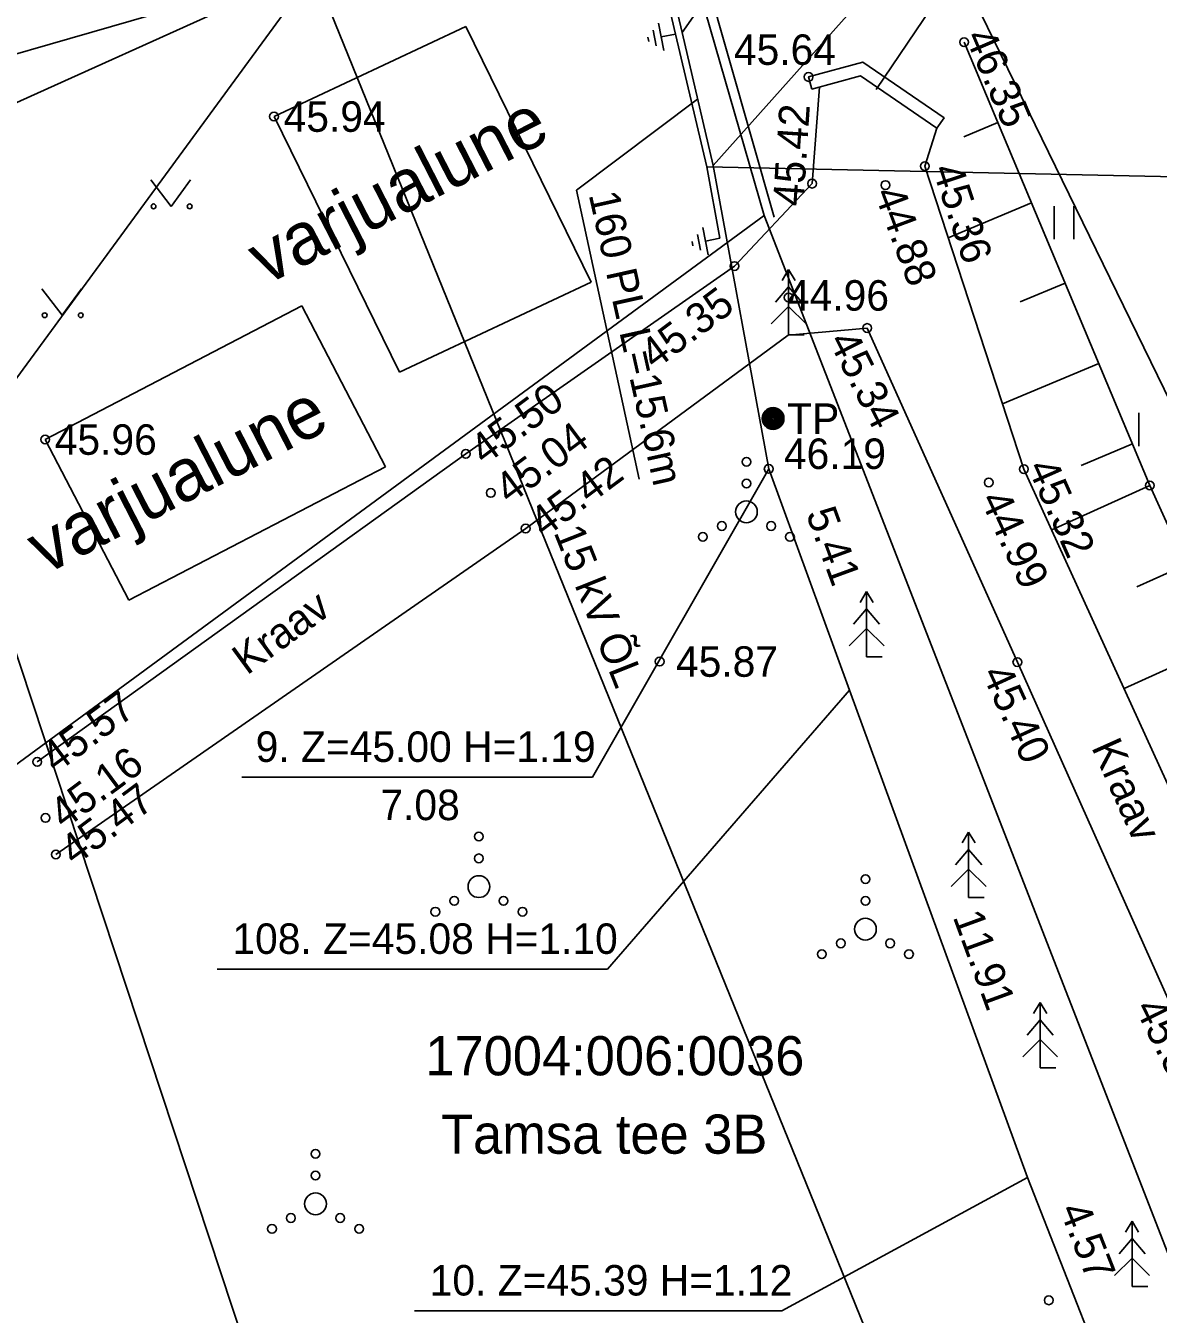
# Model space of a CAD drawing. Extents: x 642747 to 644424, y 6457048 to 6458238.
# Drawn here: x 644056.64 to 644082.64, y 6457705.93 to 6457735.52 of the extents above; entities that cross this region are included whole.
import ezdxf

# ---------------------------------------------------------------- set-up
doc = ezdxf.new("R2010")
doc.units = 0
for name, color, linetype in [('ABIJOONIS', 7, 'Continuous'), ('AED', 7, 'Continuous'), ('HALJASTUS', 7, 'Continuous'), ('HOONE', 7, 'Continuous'), ('JOONSIDE', 7, 'Continuous'), ('KOORDPUNKT', 7, 'Continuous'), ('KORGUS', 7, 'Continuous'), ('KPKAABEL', 7, 'Continuous'), ('KPOHULIIN', 7, 'Continuous'), ('MOOTPIIR', 7, 'Continuous'), ('MPKAABEL', 7, 'Continuous'), ('PIIR', 7, 'Continuous'), ('POST', 7, 'Continuous'), ('PUU', 7, 'Continuous'), ('RELJEEF', 7, 'Continuous'), ('TEE', 7, 'Continuous'), ('TRUUP', 7, 'Continuous'), ('VEEKOGU', 7, 'Continuous')]:
    doc.layers.add(name, color=color, linetype=linetype)

msp = doc.modelspace()

# ---------------------------------------------------------------- linework, layer by layer
at = {"layer": 'ABIJOONIS'}
for points in [[(644045.404, 6457721.568), (644052.131, 6457721.568), (644063.341, 6457736.874)], [(644039.301, 6457733.324), (644051.051, 6457733.324), (644062.377, 6457736.596)], [(644072.06, 6457733.834), (644069.281, 6457731.738), (644070.716, 6457725.107)], [(644072.272, 6457732.277), (644083.05, 6457732.046), (644093.848, 6457732.046)]]:
    msp.add_lwpolyline(points, dxfattribs=at)
at = {"layer": 'AED'}
msp.add_lwpolyline([(644064.587, 6457759.915), (644069.655, 6457745.733), (644073.82, 6457731.123)], dxfattribs=at)
at = {"layer": 'HALJASTUS'}
for p, q in [((644059.508, 6457731.975), (644059.971, 6457731.369)), ((644059.971, 6457731.369), (644060.417, 6457731.975)), ((644080.243, 6457731.376), (644080.243, 6457730.615)), ((644080.698, 6457731.376), (644080.698, 6457730.615)), ((644057.008, 6457729.475), (644057.471, 6457728.869)), ((644057.471, 6457728.869), (644057.917, 6457729.475)), ((644082.193, 6457726.628), (644082.193, 6457725.867))]:
    msp.add_line(p, q, dxfattribs=at)
for centre, radius in [((644059.57, 6457731.369), 0.055), ((644060.399, 6457731.369), 0.055), ((644057.07, 6457728.869), 0.055), ((644057.899, 6457728.869), 0.055), ((644073.181, 6457725.505), 0.1), ((644073.181, 6457725.005), 0.1), ((644073.181, 6457724.355), 0.25), ((644072.616, 6457724.03), 0.1), ((644073.746, 6457724.03), 0.1), ((644072.181, 6457723.78), 0.1), ((644074.181, 6457723.78), 0.1), ((644067.039, 6457716.899), 0.1), ((644067.039, 6457716.399), 0.1), ((644067.039, 6457715.749), 0.25), ((644075.913, 6457715.923), 0.1), ((644066.474, 6457715.424), 0.1), ((644067.604, 6457715.424), 0.1), ((644075.913, 6457715.423), 0.1), ((644066.039, 6457715.174), 0.1), ((644068.039, 6457715.174), 0.1), ((644075.913, 6457714.773), 0.25), ((644075.348, 6457714.448), 0.1), ((644076.478, 6457714.448), 0.1), ((644074.913, 6457714.198), 0.1), ((644076.913, 6457714.198), 0.1), ((644063.289, 6457709.616), 0.1), ((644063.289, 6457709.116), 0.1), ((644063.289, 6457708.466), 0.25), ((644062.724, 6457708.141), 0.1), ((644063.854, 6457708.141), 0.1), ((644062.289, 6457707.891), 0.1), ((644064.289, 6457707.891), 0.1), ((644080.121, 6457706.251), 0.1)]:
    msp.add_circle(centre, radius, dxfattribs=at)
at = {"layer": 'HOONE'}
for points in [[(644062.335, 6457733.431), (644066.739, 6457735.497)], [(644066.739, 6457735.497), (644069.618, 6457729.631)], [(644062.335, 6457733.431), (644065.214, 6457727.565)], [(644065.214, 6457727.565), (644069.618, 6457729.631)], [(644057.08, 6457726.015), (644062.977, 6457729.083)], [(644064.897, 6457725.392), (644062.977, 6457729.083)], [(644059, 6457722.324), (644057.08, 6457726.015)], [(644059, 6457722.324), (644064.897, 6457725.392)]]:
    msp.add_lwpolyline(points, dxfattribs=at)
at = {"layer": 'KOORDPUNKT'}
for p, q in [((644071.702, 6457735.361), (644074.389, 6457739.182)), ((644063.341, 6457736.874), (644051.03, 6457731.321)), ((644072.419, 6457732.308), (644076.502, 6457736.885)), ((644073.692, 6457725.34), (644069.649, 6457718.263)), ((644075.548, 6457720.26), (644069.989, 6457713.855)), ((644061.599, 6457718.263), (644069.649, 6457718.263)), ((644061.03, 6457713.855), (644069.989, 6457713.855)), ((644079.636, 6457709.071), (644073.995, 6457706.011)), ((644065.56, 6457706.011), (644073.995, 6457706.011))]:
    msp.add_line(p, q, dxfattribs=at)
for points in [[(644071.702, 6457735.361), (644071.702, 6457735.361), (644071.702, 6457735.361)], [(644072.419, 6457732.308), (644072.419, 6457732.308), (644072.419, 6457732.308)], [(644073.692, 6457725.34), (644073.692, 6457725.34), (644073.692, 6457725.34)], [(644075.548, 6457720.26), (644075.548, 6457720.26), (644075.548, 6457720.26)], [(644079.636, 6457709.071), (644079.636, 6457709.071), (644079.636, 6457709.071)]]:
    msp.add_lwpolyline(points, dxfattribs=at)
at = {"layer": 'KORGUS'}
for centre in [(644078.177, 6457735.139), (644074.609, 6457734.34), (644062.335, 6457733.431), (644077.278, 6457732.291), (644074.688, 6457731.891), (644076.371, 6457731.859), (644072.906, 6457729.999), (644074.15, 6457729.278), (644075.952, 6457728.576), (644057.08, 6457726.015), (644066.738, 6457725.687), (644073.692, 6457725.34), (644079.553, 6457725.335), (644078.744, 6457725.03), (644067.311, 6457724.789), (644082.441, 6457724.961), (644068.113, 6457723.971), (644071.189, 6457720.918), (644079.401, 6457720.905), (644056.9, 6457718.615), (644057.087, 6457717.327), (644057.327, 6457716.488)]:
    msp.add_circle(centre, 0.1, dxfattribs=at)
at = {"layer": 'KPKAABEL'}
for points in [[(644063.341, 6457736.874), (644063.814, 6457738.243), (644064.085, 6457738.786), (644069.675, 6457740.685), (644070.251, 6457740.516), (644070.657, 6457739.804), (644071.702, 6457735.361), (644072.419, 6457732.308), (644073.692, 6457725.34), (644075.548, 6457720.26), (644079.636, 6457709.071), (644081.299, 6457704.816), (644084.417, 6457695.285), (644092.153, 6457678.564), (644095.564, 6457671.153), (644098.741, 6457664.129), (644103.079, 6457652.715), (644111.131, 6457630.665)], [(644071.702, 6457735.361), (644072.419, 6457732.308), (644073.692, 6457725.34), (644075.548, 6457720.26)]]:
    msp.add_lwpolyline(points, dxfattribs=at)
at = {"layer": 'KPOHULIIN'}
msp.add_lwpolyline([(644061.981, 6457739.913), (644094.239, 6457660.452), (644124.342, 6457586.031), (644125.691, 6457582.672)], dxfattribs=at)
at = {"layer": 'MOOTPIIR'}
msp.add_lwpolyline([(643525.446, 6457467.559), (643537.447, 6457435.458), (643944.848, 6457628.51), (644046.626, 6457529.09), (644067.022, 6457529.09), (644138.408, 6457598.401), (644075.1, 6457775.215), (644046.02, 6457752.582), (644092.466, 6457611.94), (644070.657, 6457576.375), (644041.981, 6457570.717), (643942.223, 6457662.862)], close=True, dxfattribs=at)
at = {"layer": 'MPKAABEL'}
for points in [[(644063.341, 6457736.874), (644063.525, 6457737.126), (644063.885, 6457737.955), (644064.192, 6457738.663), (644067.431, 6457739.764), (644069.678, 6457740.527), (644070.15, 6457740.388), (644070.516, 6457739.748), (644071.555, 6457735.326), (644072.272, 6457732.277), (644072.571, 6457730.636)], [(644071.284, 6457734.949), (644071.161, 6457735.573)], [(644070.937, 6457735.154), (644070.918, 6457735.252)], [(644071.11, 6457735.052), (644071.039, 6457735.413)], [(644071.555, 6457735.326), (644071.222, 6457735.261)], [(644072.127, 6457730.361), (644072.056, 6457730.722)], [(644072.3, 6457730.259), (644072.177, 6457730.883)], [(644071.954, 6457730.464), (644071.935, 6457730.562)], [(644072.571, 6457730.636), (644072.239, 6457730.571)]]:
    msp.add_lwpolyline(points, dxfattribs=at)
at = {"layer": 'PIIR'}
msp.add_lwpolyline([(644056.78, 6457779.28), (644062.47, 6457766.56), (644060.34, 6457762.97), (644041.41, 6457742.89), (644054.5, 6457738.54), (644058.72, 6457740.17), (644055.31, 6457749.58), (644061, 6457751.62), (644060.21, 6457753.82), (644065.16, 6457760.36), (644069.76, 6457744.43), (644073.59, 6457731.16), (644087.56, 6457695.23), (644092.09, 6457697.08), (644102.74, 6457676.12), (644108.68, 6457668.18), (644119.21, 6457655.5), (644137.18, 6457639.57)], dxfattribs=at)
for points in [[(643989.66, 6457760.08), (643987.33, 6457763.78), (643977.05, 6457733.09), (644043.85, 6457709.33), (644073.59, 6457731.16), (644069.76, 6457744.43), (644054.5, 6457738.54), (644041.41, 6457742.89)], [(644073.59, 6457731.16), (644043.85, 6457709.33), (644087.56, 6457695.23)]]:
    msp.add_lwpolyline(points, close=True, dxfattribs=at)
at = {"layer": 'POST'}
for radius in [0.25, 0.225, 0.2, 0.175, 0.15, 0.125, 0.1, 0.075, 0.05, 0.025]:
    msp.add_circle((644073.792, 6457726.498), radius, dxfattribs=at)
at = {"layer": 'PUU'}
for p, q in [((644074.15, 6457729.919), (644074, 6457729.669)), ((644074.3, 6457729.669), (644074.15, 6457729.919)), ((644074.15, 6457729.919), (644074.15, 6457728.419)), ((644074.15, 6457729.519), (644073.85, 6457729.169)), ((644074.45, 6457729.169), (644074.15, 6457729.519)), ((644074.15, 6457729.069), (644073.75, 6457728.669)), ((644074.55, 6457728.669), (644074.15, 6457729.069)), ((644074.51, 6457728.419), (644074.15, 6457728.419)), ((644075.94, 6457722.526), (644075.79, 6457722.276)), ((644076.09, 6457722.276), (644075.94, 6457722.526)), ((644075.94, 6457722.526), (644075.94, 6457721.026)), ((644075.94, 6457722.126), (644075.64, 6457721.776)), ((644076.24, 6457721.776), (644075.94, 6457722.126)), ((644075.94, 6457721.676), (644075.54, 6457721.276)), ((644076.34, 6457721.276), (644075.94, 6457721.676)), ((644076.3, 6457721.026), (644075.94, 6457721.026)), ((644078.282, 6457717.002), (644078.132, 6457716.752)), ((644078.432, 6457716.752), (644078.282, 6457717.002)), ((644078.282, 6457717.002), (644078.282, 6457715.502)), ((644078.282, 6457716.602), (644077.982, 6457716.252)), ((644078.582, 6457716.252), (644078.282, 6457716.602)), ((644078.282, 6457716.152), (644077.882, 6457715.752)), ((644078.682, 6457715.752), (644078.282, 6457716.152)), ((644078.642, 6457715.502), (644078.282, 6457715.502)), ((644079.925, 6457713.089), (644079.775, 6457712.839)), ((644080.075, 6457712.839), (644079.925, 6457713.089)), ((644079.925, 6457713.089), (644079.925, 6457711.589)), ((644079.925, 6457712.689), (644079.625, 6457712.339)), ((644080.225, 6457712.339), (644079.925, 6457712.689)), ((644079.925, 6457712.239), (644079.525, 6457711.839)), ((644080.325, 6457711.839), (644079.925, 6457712.239)), ((644080.285, 6457711.589), (644079.925, 6457711.589)), ((644082.035, 6457708.068), (644081.885, 6457707.818)), ((644082.185, 6457707.818), (644082.035, 6457708.068)), ((644082.035, 6457708.068), (644082.035, 6457706.568)), ((644082.035, 6457707.668), (644081.735, 6457707.318)), ((644082.335, 6457707.318), (644082.035, 6457707.668)), ((644082.035, 6457707.218), (644081.635, 6457706.818)), ((644082.435, 6457706.818), (644082.035, 6457707.218)), ((644082.395, 6457706.568), (644082.035, 6457706.568))]:
    msp.add_line(p, q, dxfattribs=at)
at = {"layer": 'RELJEEF'}
for p, q in [((644078.95, 6457733.294), (644078.169, 6457732.967)), ((644079.723, 6457731.45), (644077.815, 6457730.65)), ((644080.495, 6457729.605), (644079.467, 6457729.174)), ((644081.268, 6457727.76), (644079.062, 6457726.836)), ((644082.041, 6457725.916), (644080.863, 6457725.422)), ((644082.441, 6457724.961), (644080.189, 6457723.941)), ((644083.267, 6457723.14), (644082.143, 6457722.631)), ((644084.092, 6457721.318), (644081.85, 6457720.302))]:
    msp.add_line(p, q, dxfattribs=at)
msp.add_lwpolyline([(644078.177, 6457735.139), (644082.441, 6457724.961), (644086.313, 6457716.42), (644093.19, 6457702.456), (644098.75, 6457688.389)], dxfattribs=at)
at = {"layer": 'TEE'}
msp.add_lwpolyline([(644061.722, 6457771.823), (644064.397, 6457766.262), (644069.452, 6457755.916), (644076.842, 6457739.337), (644084.183, 6457724.283), (644091.562, 6457708.571), (644100.441, 6457690.483), (644108.831, 6457675.729), (644120.122, 6457661.417), (644128.409, 6457653.611)], dxfattribs=at)
at = {"layer": 'TRUUP'}
msp.add_line((644076.161, 6457734.051), (644081.798, 6457742.429), dxfattribs=at)
for points in [[(644074.686, 6457734.059), (644074.609, 6457734.34), (644075.85, 6457734.682), (644077.718, 6457733.402), (644077.554, 6457733.162)], [(644074.686, 6457734.059), (644075.797, 6457734.365), (644077.554, 6457733.162)]]:
    msp.add_lwpolyline(points, dxfattribs=at)
at = {"layer": 'VEEKOGU'}
for points in [[(644066.738, 6457725.687), (644072.906, 6457729.999), (644074.688, 6457731.891), (644074.862, 6457734.108)], [(644097.313, 6457685.871), (644090.771, 6457700.745), (644084.984, 6457713.434), (644079.553, 6457725.335), (644077.278, 6457732.291), (644077.554, 6457733.162)], [(644093.965, 6457689.322), (644087.455, 6457703.827), (644082.892, 6457713.097), (644079.401, 6457720.905), (644075.952, 6457728.576), (644074.141, 6457728.409), (644068.113, 6457723.971)], [(644056.9, 6457718.615), (644066.738, 6457725.687)], [(644057.327, 6457716.488), (644068.113, 6457723.971)]]:
    msp.add_lwpolyline(points, dxfattribs=at)

# ---------------------------------------------------------------- texts
at = {"layer": 'ABIJOONIS'}
msp.add_text('160 PL L=15.6m', height=0.7, rotation=282.5781, dxfattribs=at).set_placement((644069.557, 6457731.641))
at = {"layer": 'HOONE'}
for p in [(644062.145, 6457729.549), (644057.077, 6457722.902)]:
    msp.add_text('varjualune', height=1.2, rotation=27.1657, dxfattribs=at).set_placement(p)
at = {"layer": 'JOONSIDE'}
for s, rotation, p in [('5.41', 290.0702, (644074.54, 6457724.316)), ('11.91', 290.0702, (644077.913, 6457715.058)), ('4.57', 291.3473, (644080.361, 6457708.336))]:
    msp.add_text(s, height=0.7, rotation=rotation, dxfattribs=at).set_placement(p)
msp.add_text('7.08', height=0.7, dxfattribs=at).set_placement((644064.778, 6457717.276))
at = {"layer": 'KOORDPUNKT'}
for s, p in [('9. Z=45.00 H=1.19', (644061.914, 6457718.613)), ('108. Z=45.08 H=1.10', (644061.38, 6457714.205)), ('10. Z=45.39 H=1.12', (644065.91, 6457706.361))]:
    msp.add_text(s, height=0.7, dxfattribs=at).set_placement(p)
at = {"layer": 'KORGUS'}
for s, p in [(' 45.64', (644072.634, 6457734.618)), ('45.94', (644062.556, 6457733.081)), (' 44.96', (644073.852, 6457728.975)), ('45.96', (644057.301, 6457725.665)), ('46.19', (644074.042, 6457725.34)), ('45.87', (644071.564, 6457720.568))]:
    msp.add_text(s, height=0.7, dxfattribs=at).set_placement(p)
for s, rotation, p in [(' 46.35', 293.1495, (644078.089, 6457735.508)), (' 45.42', 86.2195, (644074.468, 6457731.098)), (' 45.36', 288.3446, (644077.362, 6457732.471)), (' 44.88', 290.4151, (644076.018, 6457731.918)), (' 45.35', 36.9373, (644070.871, 6457727.442)), (' 45.34', 296.8434, (644074.937, 6457728.518)), ('45.50', 36.7396, (644067.169, 6457725.407)), ('45.04', 36.7396, (644067.742, 6457724.509)), ('45.42', 36.7396, (644068.539, 6457723.737)), (' 45.32', 293.8325, (644079.519, 6457725.62)), (' 44.99', 294.7939, (644078.427, 6457724.883)), (' 45.40', 294.6546, (644078.465, 6457720.88)), ('45.57', 36.7396, (644057.331, 6457718.335)), ('45.16', 36.7396, (644057.518, 6457717.047)), ('45.47', 36.7396, (644057.758, 6457716.208)), (' 45.38', 296.3474, (644081.971, 6457713.203))]:
    msp.add_text(s, height=0.7, rotation=rotation, dxfattribs=at).set_placement(p)
at = {"layer": 'KPOHULIIN'}
msp.add_text('15 kV ÕL', height=0.7, rotation=291.7007, dxfattribs=at).set_placement((644068.749, 6457723.886))
at = {"layer": 'PIIR'}
for s, p in [('17004:006:0036', (644065.81, 6457711.417)), ('Tamsa tee 3B', (644066.17, 6457709.617))]:
    msp.add_text(s, height=0.9, dxfattribs=at).set_placement(p)
at = {"layer": 'POST'}
msp.add_text('TP', height=0.7, dxfattribs=at).set_placement((644074.117, 6457726.145))
at = {"layer": 'VEEKOGU'}
for rotation, p in [(36.2418, (644061.713, 6457720.591)), (294.0944, (644081.092, 6457718.952))]:
    msp.add_text('Kraav', height=0.7, rotation=rotation, dxfattribs=at).set_placement(p)

doc.saveas('drawing.dxf')
